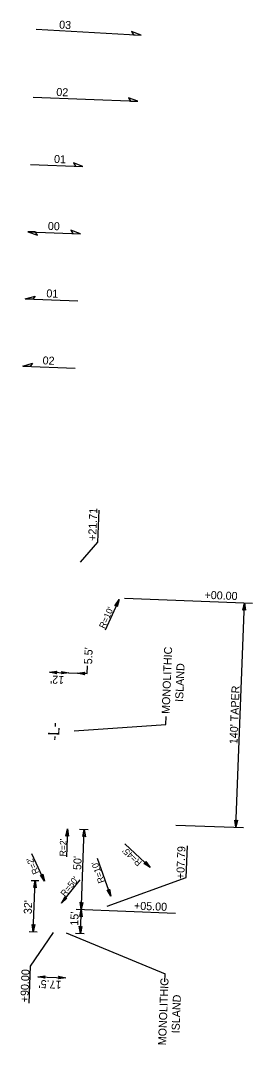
# Model space of a CAD drawing. Extents: x 2096941 to 2098098, y 685096 to 689626.
# Drawn here: x 2097745 to 2097890, y 687938 to 688578 of the extents above; entities that cross this region are included whole.
import ezdxf

# ---------------------------------------------------------------- set-up
doc = ezdxf.new("R2010")
doc.units = 0
for name, color, linetype in [('Prop Dimension', 7, 'Continuous'), ('Prop Dimension Text', 7, 'Continuous'), ('Prop Horizontal Alignment Direction Label', 7, 'Continuous'), ('Prop Superelevation  Arrow CELL', 7, 'Continuous'), ('Prop Superelevation Label', 7, 'Continuous'), ('Prop Terminator CELL', 7, 'Continuous')]:
    doc.layers.add(name, color=color, linetype=linetype)

msp = doc.modelspace()

# ---------------------------------------------------------------- linework, layer by layer
at = {"layer": 'Prop Dimension'}
for p, q in [((2097792.98, 688251.73), (2097793.74, 688271.66)), ((2097782.16, 688239.2), (2097792.98, 688251.73)), ((2097809.66, 688216.68), (2097889.51, 688213.61)), ((2097806.23, 688215.85), (2097797.45, 688196.71)), ((2097879.12, 688073.65), (2097884.49, 688213.81)), ((2097786.39, 688169.65), (2097786.57, 688174.43)), ((2097762.77, 688170.56), (2097786.39, 688169.65)), ((2097835.32, 688137.86), (2097835.51, 688142.85)), ((2097778.13, 688133.89), (2097835.32, 688137.86)), ((2097773.93, 688072.69), (2097773.42, 688055.22)), ((2097781.43, 688072.46), (2097786.87, 688072.25)), ((2097782.03, 688007.33), (2097784.52, 688072.34)), ((2097841.61, 688075.09), (2097883.98, 688073.47)), ((2097825.6, 688048.58), (2097809.78, 688063.3)), ((2097759.72, 688040.04), (2097751.85, 688057.15)), ((2097848.08, 688042.21), (2097848.84, 688062.14)), ((2097801.03, 688030.54), (2097792.73, 688054.07)), ((2097751.3, 688040.53), (2097756.22, 688040.34)), ((2097752.65, 688008.45), (2097753.88, 688040.43)), ((2097770.27, 688026.37), (2097781.9, 688040.85)), ((2097798.7, 688024.49), (2097848.08, 688042.21)), ((2097779.51, 688022.43), (2097841.53, 688020.06)), ((2097750.07, 688008.55), (2097754.99, 688008.36)), ((2097750.98, 687986.97), (2097765.29, 688007.97)), ((2097773.28, 688007.66), (2097835.03, 687982.14)), ((2097778.93, 688007.45), (2097784.37, 688007.24)), ((2097750.09, 687963.89), (2097750.98, 687986.97)), ((2097755.47, 687980.35), (2097772.96, 687979.68)), ((2097834.84, 687977.15), (2097835.03, 687982.14))]:
    msp.add_line(p, q, dxfattribs=at)
at = {"layer": 'Prop Superelevation  Arrow CELL'}
for p, q in [((2097754.54, 688572.19), (2097819.94, 688568.49)), ((2097752.52, 688529.64), (2097817.97, 688527.13)), ((2097750.91, 688487.67), (2097783.64, 688486.42)), ((2097749.3, 688445.7), (2097782.03, 688444.45)), ((2097747.69, 688403.73), (2097780.42, 688402.48)), ((2097746.08, 688361.76), (2097778.81, 688360.51))]:
    msp.add_line(p, q, dxfattribs=at)
for points in [[(2097819.94, 688568.49), (2097814.06, 688570.82), (2097815.32, 688568.75)], [(2097817.97, 688527.13), (2097812.06, 688529.36), (2097813.35, 688527.31)], [(2097783.64, 688486.42), (2097777.72, 688488.65), (2097779.02, 688486.59)], [(2097749.3, 688445.7), (2097755.22, 688443.47), (2097753.93, 688445.53)], [(2097782.03, 688444.45), (2097776.11, 688446.68), (2097777.41, 688444.62)], [(2097747.69, 688403.73), (2097753.77, 688405.5), (2097752.32, 688403.56)], [(2097746.08, 688361.76), (2097752.16, 688363.53), (2097750.71, 688361.59)]]:
    msp.add_lwpolyline(points, close=True, dxfattribs=at)
at = {"layer": 'Prop Terminator CELL'}
for points in [[(2097803.65, 688212.08), (2097806.23, 688215.85), (2097805.07, 688211.4), (2097804.58, 688212.26)], [(2097883.55, 688209.34), (2097884.49, 688213.81), (2097885.12, 688209.25), (2097884.34, 688209.86)], [(2097767.24, 688169.61), (2097762.77, 688170.56), (2097767.32, 688171.18), (2097766.72, 688170.41)], [(2097770.29, 688171.04), (2097774.76, 688170.1), (2097770.21, 688169.47), (2097770.81, 688170.25)], [(2097784.72, 688168.94), (2097780.26, 688169.89), (2097784.81, 688170.51), (2097784.2, 688169.74)], [(2097880.06, 688078.12), (2097879.12, 688073.65), (2097878.49, 688078.21), (2097879.27, 688077.6)], [(2097773.03, 688068.22), (2097773.93, 688072.69), (2097774.6, 688068.14), (2097773.82, 688068.74)], [(2097783.58, 688067.88), (2097784.52, 688072.34), (2097785.15, 688067.79), (2097784.37, 688068.4)], [(2097822.83, 688052.22), (2097825.6, 688048.58), (2097821.74, 688051.08), (2097822.71, 688051.27)], [(2097758.55, 688044.45), (2097759.72, 688040.04), (2097757.11, 688043.82), (2097758.07, 688043.63)], [(2097752.93, 688035.96), (2097753.88, 688040.43), (2097754.5, 688035.88), (2097753.72, 688036.48)], [(2097800.26, 688035.04), (2097801.03, 688030.54), (2097798.77, 688034.54), (2097799.71, 688034.26)], [(2097773.69, 688029.4), (2097770.27, 688026.37), (2097772.48, 688030.4), (2097772.75, 688029.45)], [(2097783.55, 688026.78), (2097782.61, 688022.32), (2097781.98, 688026.87), (2097782.76, 688026.26)], [(2097781.66, 688017.85), (2097782.61, 688022.32), (2097783.23, 688017.76), (2097782.45, 688018.37)], [(2097753.6, 688012.92), (2097752.65, 688008.45), (2097752.02, 688013.01), (2097752.8, 688012.4)], [(2097782.98, 688011.79), (2097782.03, 688007.33), (2097781.4, 688011.88), (2097782.18, 688011.27)], [(2097759.94, 687979.41), (2097755.47, 687980.35), (2097760.03, 687980.98), (2097759.42, 687980.2)], [(2097768.49, 687980.63), (2097772.96, 687979.68), (2097768.41, 687979.06), (2097769.01, 687979.83)]]:
    msp.add_lwpolyline(points, close=True, dxfattribs=at)

# ---------------------------------------------------------------- texts
at = {"layer": 'Prop Dimension Text'}
for s, height, rotation, p in [('+21.71', 5, 87.8037, (2097791.86, 688252.47)), ('+00.00', 5, 357.8037, (2097859.46, 688216.38)), ("R=10'", 4, 65.37688, (2097797.16, 688197.44)), ("5.5'", 5, 87.8037, (2097789.36, 688175.41)), ('MONOLITHIC', 5, 87.8037, (2097837.77, 688144.43)), ('ISLAND', 5, 87.8037, (2097846.18, 688151.91)), ("12'", 5, 177.8037, (2097772.03, 688168.11)), ("140' TAPER", 5, 87.8037, (2097880.08, 688125.5)), ("R=2'", 4, 88.33483, (2097773.01, 688055.47)), ("R=45'", 4, 137.05607, (2097820.69, 688051.9)), ('+07.79', 5, 87.8037, (2097846.89, 688041.18)), ("R=2'", 4, 114.70708, (2097756.38, 688045.39)), ("50'", 5, 87.8037, (2097782.52, 688046.9)), ("R=10'", 4, 109.42564, (2097797.22, 688039.57)), ("R=50'", 4, 51.21973, (2097772.43, 688030.02)), ("32'", 5, 87.8037, (2097751.66, 688019.34)), ('+05.00', 5, 357.8037, (2097815.47, 688022.24)), ("15'", 5, 87.8037, (2097780.68, 688012.15)), ('+90.00', 5, 87.8037, (2097749.55, 687964.31)), ("17.5'", 5, 177.8037, (2097770.35, 687977.76)), ('MONOLITHIC', 5, 87.8037, (2097835.51, 687937.43)), ('ISLAND', 5, 87.8037, (2097843.93, 687944.91))]:
    msp.add_text(s, height=height, rotation=rotation, dxfattribs=at).set_placement(p)
at = {"layer": 'Prop Horizontal Alignment Direction Label'}
msp.add_text('-L-', height=7, rotation=87.8037, dxfattribs=at).set_placement((2097768.76, 688127.68))
at = {"layer": 'Prop Superelevation Label'}
for s, rotation, p in [('03', 356.67283, (2097768.69, 688572.61)), ('02', 357.71903, (2097766.95, 688530.51)), ('01', 357.71903, (2097765.52, 688488.68)), ('00', 357.71903, (2097761.68, 688446.83)), ('01', 357.71903, (2097760.75, 688404.71)), ('02', 357.71903, (2097758.4, 688362.84))]:
    msp.add_text(s, height=5, rotation=rotation, dxfattribs=at).set_placement(p)

doc.saveas('drawing.dxf')
